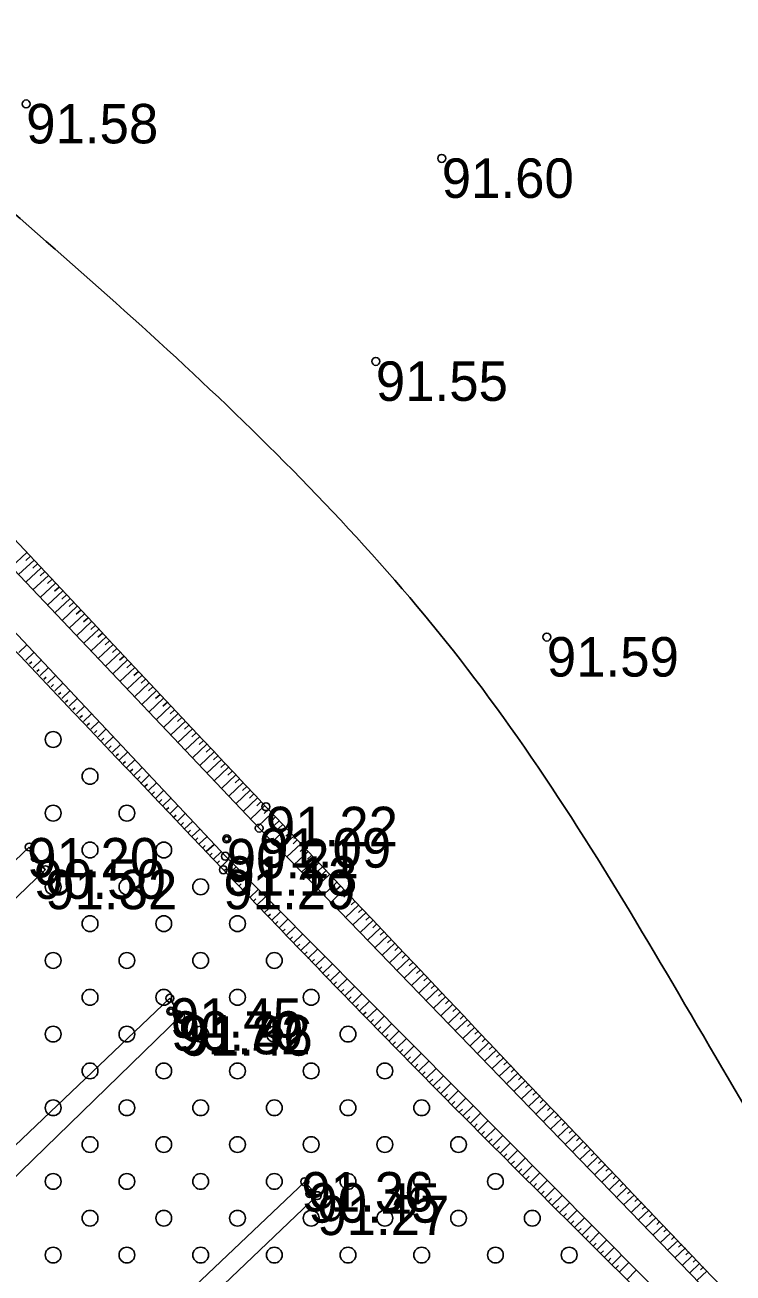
# Model space of a CAD drawing. Extents: x 316000 to 728450, y 314368 to 726000.
# Drawn here: x 726040.8 to 726108.1, y 315253.8 to 315372.4 of the extents above; entities that cross this region are included whole.
import ezdxf

# ---------------------------------------------------------------- set-up
doc = ezdxf.new("R2010")
doc.units = 0
for name, color, linetype in [('HIDG_ELEM_####_####_#', 7, 'Continuous'), ('HIDG_GRAV_####_####_#', 7, 'Continuous'), ('RELJ_AATZ_####_TKST_#', 7, 'Continuous'), ('RELJ_ELEM_####_####_#', 7, 'Continuous'), ('RELJ_HORZ_PAMT_####_#', 7, 'Continuous'), ('RELJ_NOGA_####_####_#', 7, 'Continuous'), ('TERT_ELEM_####_####_#', 7, 'Continuous')]:
    doc.layers.add(name, color=color, linetype=linetype)

msp = doc.modelspace()

# ---------------------------------------------------------------- linework, layer by layer
at = {"layer": 'HIDG_ELEM_####_####_#'}
for centre in [(726059.98, 315295.05), (726041.65, 315293.15), (726054.68, 315278.67), (726067.87, 315261.34)]:
    msp.add_circle(centre, 0.225, dxfattribs=at)
at = {"layer": 'HIDG_GRAV_####_####_#'}
for points in [[(726259.18, 315086.52), (726260.77, 315088.86), (726179.01, 315175.77), (726127.86, 315229.06), (726063.06, 315296.07), (725998.34, 315364.32), (725936.65, 315430.32), (725875.35, 315494.08), (725809.44, 315562.19), (725743.94, 315631.87)], [(725741.16, 315628.11), (725806.06, 315558.99), (725870.9, 315491.87), (725934.12, 315427.08), (725995.78, 315361.63), (726059.85, 315293.4), (726126.03, 315226.73), (726194.49, 315154.86), (726259.18, 315086.52)], [(726041.22, 315294.28), (726042.74, 315292.12), (725933.2, 315186.57), (725862.99, 315121.84), (725861.5, 315123.44), (725931.43, 315189.54), (726041.22, 315294.28)], [(726054.58, 315279.91), (726055.6, 315278.2), (725943.43, 315169.03), (725940.91, 315171.62), (726054.58, 315279.91)], [(726067.39, 315262.47), (726068.58, 315261.15), (725954.8, 315152.62), (725890.85, 315090.51), (725889.28, 315091.99), (725953.78, 315154.65), (726067.39, 315262.47)]]:
    msp.add_lwpolyline(points, dxfattribs=at)
at = {"layer": 'RELJ_ELEM_####_####_#'}
for centre in [(726040.93, 315364.9), (726080.4, 315359.72), (726074.14, 315340.43), (726090.38, 315314.23), (726063.7, 315298.11), (726063.06, 315296.07), (726059.98, 315295.05), (726041.22, 315294.28), (726059.85, 315293.4), (726042.74, 315292.12), (726059.66, 315292.12), (726054.58, 315279.91), (726054.68, 315278.67), (726055.39, 315278.33), (726055.6, 315278.2), (726067.39, 315262.47), (726067.87, 315261.34), (726068.58, 315261.15)]:
    msp.add_circle(centre, 0.375, dxfattribs=at)
at = {"layer": 'RELJ_HORZ_PAMT_####_#'}
for points in [[(726116.34, 315699.09), (726105.94, 315702.69), (726040.13, 315715), (725990.82, 315710.42), (725942.03, 315708.25), (725920.28, 315706.77), (725880.37, 315714.51), (725859.05, 315708.68), (725859.05, 315672.66), (725851.26, 315613.97), (725853.47, 315568.9), (725841, 315555.79), (725885.56, 315509.63), (725935.94, 315461.49), (725983.42, 315406.25), (726032.86, 315360.51), (726082.85, 315311.19), (726122.23, 315248.76), (726137.05, 315229.29), (726180.19, 315183.1), (726194.52, 315168.27), (726211.91, 315146.93), (726212.51, 315143.16)], [(726081.57, 315247.05), (726057.5, 315241.5), (726036.5, 315213.5), (725977, 315161), (725966.5, 315108.5), (725903.5, 315045.5), (725862.12, 315076.6), (725805.5, 315130), (725759.7, 315178.88), (725709.89, 315228.8), (725646.99, 315287.19), (725634.68, 315314.96), (725629.04, 315327.48), (725557.35, 315340.26), (725478.3, 315344.16)]]:
    msp.add_spline(points, degree=3, dxfattribs=at)
at = {"layer": 'RELJ_NOGA_####_####_#'}
for p, q in [((726041, 315322.28), (726039.52, 315320.89)), ((726041.68, 315321.55), (726040.21, 315320.17)), ((726041.34, 315321.91), (726040.89, 315321.5)), ((726042.02, 315321.18), (726041.58, 315320.77)), ((726042.36, 315320.82), (726040.89, 315319.44)), ((726043.05, 315320.09), (726041.58, 315318.72)), ((726042.7, 315320.45), (726042.26, 315320.04)), ((726043.73, 315319.36), (726042.27, 315317.99)), ((726043.39, 315319.72), (726042.95, 315319.31)), ((726044.07, 315318.99), (726043.63, 315318.58)), ((726044.41, 315318.63), (726042.96, 315317.26)), ((726045.1, 315317.9), (726043.65, 315316.54)), ((726044.76, 315318.26), (726044.32, 315317.85)), ((726045.44, 315317.53), (726045, 315317.13)), ((726045.78, 315317.17), (726044.34, 315315.81)), ((726046.46, 315316.44), (726045.02, 315315.09)), ((726046.12, 315316.8), (726045.69, 315316.4)), ((726047.15, 315315.71), (726045.71, 315314.36)), ((726046.81, 315316.07), (726046.38, 315315.67)), ((726047.49, 315315.34), (726047.06, 315314.94)), ((726047.83, 315314.98), (726046.4, 315313.64)), ((726048.52, 315314.25), (726047.09, 315312.91)), ((726048.17, 315314.61), (726047.75, 315314.21)), ((726040.22, 315312.77), (726040.98, 315313.49)), ((726040.9, 315312.04), (726041.66, 315312.76)), ((726049.2, 315313.52), (726047.78, 315312.18)), ((726048.86, 315313.88), (726048.43, 315313.48)), ((726049.89, 315312.79), (726048.47, 315311.46)), ((726049.54, 315313.16), (726049.12, 315312.75)), ((726041.24, 315311.68), (726041.47, 315311.89)), ((726041.59, 315311.31), (726042.35, 315312.03)), ((726050.57, 315312.06), (726049.15, 315310.73)), ((726050.23, 315312.43), (726049.8, 315312.03)), ((726050.91, 315311.7), (726050.49, 315311.3)), ((726041.93, 315310.95), (726042.16, 315311.16)), ((726042.27, 315310.58), (726043.03, 315311.3)), ((726042.61, 315310.22), (726042.84, 315310.43)), ((726042.96, 315309.86), (726043.72, 315310.57)), ((726051.25, 315311.33), (726049.84, 315310.01)), ((726051.94, 315310.6), (726050.53, 315309.28)), ((726051.6, 315310.97), (726051.17, 315310.57)), ((726043.3, 315309.49), (726043.53, 315309.71)), ((726043.64, 315309.13), (726044.4, 315309.84)), ((726052.62, 315309.87), (726051.22, 315308.55)), ((726052.28, 315310.24), (726051.86, 315309.84)), ((726052.97, 315309.51), (726052.54, 315309.11)), ((726043.99, 315308.76), (726044.21, 315308.98)), ((726044.33, 315308.4), (726045.09, 315309.11)), ((726044.67, 315308.03), (726044.9, 315308.25)), ((726045.01, 315307.67), (726045.77, 315308.38)), ((726053.31, 315309.15), (726051.91, 315307.83)), ((726053.99, 315308.42), (726052.59, 315307.1)), ((726053.65, 315308.78), (726053.23, 315308.39)), ((726054.34, 315308.05), (726053.92, 315307.66)), ((726045.36, 315307.31), (726045.58, 315307.52)), ((726045.7, 315306.94), (726046.46, 315307.66)), ((726046.04, 315306.58), (726046.27, 315306.79)), ((726046.38, 315306.21), (726047.14, 315306.93)), ((726054.68, 315307.69), (726053.28, 315306.38)), ((726055.36, 315306.96), (726053.97, 315305.65)), ((726055.02, 315307.32), (726054.6, 315306.93)), ((726046.73, 315305.85), (726046.95, 315306.06)), ((726047.07, 315305.49), (726047.83, 315306.2)), ((726056.05, 315306.23), (726054.66, 315304.93)), ((726055.71, 315306.6), (726055.29, 315306.2)), ((726056.39, 315305.87), (726055.97, 315305.48)), ((726047.41, 315305.12), (726047.64, 315305.34)), ((726047.76, 315304.76), (726048.51, 315305.47)), ((726048.1, 315304.39), (726048.32, 315304.61)), ((726048.44, 315304.03), (726049.19, 315304.74)), ((726056.73, 315305.5), (726055.35, 315304.2)), ((726057.42, 315304.77), (726056.04, 315303.47)), ((726057.08, 315305.14), (726056.66, 315304.75)), ((726048.78, 315303.67), (726049.01, 315303.88)), ((726049.13, 315303.3), (726049.88, 315304.01)), ((726049.81, 315302.57), (726050.56, 315303.28)), ((726058.1, 315304.05), (726056.72, 315302.75)), ((726057.76, 315304.41), (726057.35, 315304.02)), ((726058.79, 315303.32), (726057.41, 315302.02)), ((726058.45, 315303.68), (726058.03, 315303.29)), ((726049.47, 315302.94), (726049.69, 315303.15)), ((726050.15, 315302.21), (726050.38, 315302.42)), ((726050.5, 315301.85), (726051.25, 315302.55)), ((726059.48, 315302.59), (726058.1, 315301.3)), ((726059.13, 315302.95), (726058.72, 315302.57)), ((726059.82, 315302.23), (726059.41, 315301.84)), ((726050.84, 315301.48), (726051.07, 315301.69)), ((726051.18, 315301.12), (726051.93, 315301.82)), ((726051.53, 315300.75), (726051.75, 315300.97)), ((726051.87, 315300.39), (726052.62, 315301.1)), ((726060.16, 315301.86), (726058.79, 315300.57)), ((726060.85, 315301.14), (726059.48, 315299.84)), ((726060.5, 315301.5), (726060.09, 315301.11)), ((726052.21, 315300.03), (726052.44, 315300.24)), ((726052.55, 315299.66), (726053.3, 315300.37)), ((726061.53, 315300.41), (726060.17, 315299.12)), ((726061.19, 315300.77), (726060.78, 315300.38)), ((726062.22, 315299.68), (726060.85, 315298.39)), ((726061.88, 315300.04), (726061.47, 315299.66)), ((726052.9, 315299.3), (726053.12, 315299.51)), ((726053.24, 315298.93), (726053.99, 315299.64)), ((726053.58, 315298.57), (726053.81, 315298.78)), ((726053.93, 315298.21), (726054.67, 315298.91)), ((726062.91, 315298.95), (726061.54, 315297.67)), ((726062.56, 315299.32), (726062.15, 315298.93)), ((726063.25, 315298.59), (726062.84, 315298.2)), ((726054.27, 315297.84), (726054.49, 315298.05)), ((726054.61, 315297.48), (726055.35, 315298.18)), ((726054.95, 315297.11), (726055.18, 315297.32)), ((726055.3, 315296.75), (726056.04, 315297.45)), ((726063.59, 315298.23), (726062.23, 315296.94)), ((726064.28, 315297.5), (726062.92, 315296.22)), ((726063.94, 315297.86), (726063.53, 315297.48)), ((726055.64, 315296.39), (726055.86, 315296.6)), ((726055.98, 315296.02), (726056.72, 315296.72)), ((726064.97, 315296.77), (726063.61, 315295.5)), ((726064.62, 315297.14), (726064.22, 315296.75)), ((726065.31, 315296.41), (726064.9, 315296.03)), ((726056.33, 315295.66), (726056.55, 315295.87)), ((726056.67, 315295.29), (726057.41, 315295.99)), ((726057.01, 315294.93), (726057.23, 315295.14)), ((726057.35, 315294.57), (726058.09, 315295.26)), ((726065.65, 315296.04), (726064.31, 315294.78)), ((726066.34, 315295.32), (726065, 315294.06)), ((726066, 315295.68), (726065.59, 315295.3)), ((726066.68, 315294.95), (726066.28, 315294.58)), ((726057.7, 315294.2), (726057.92, 315294.41)), ((726058.04, 315293.84), (726058.78, 315294.53)), ((726058.73, 315293.11), (726059.46, 315293.81)), ((726067.03, 315294.59), (726065.7, 315293.34)), ((726067.71, 315293.86), (726066.39, 315292.62)), ((726067.37, 315294.23), (726066.97, 315293.85)), ((726058.38, 315293.48), (726058.6, 315293.68)), ((726059.07, 315292.75), (726059.29, 315292.96)), ((726059.41, 315292.38), (726060.16, 315293.08)), ((726068.4, 315293.14), (726067.09, 315291.9)), ((726068.06, 315293.5), (726067.66, 315293.13)), ((726068.74, 315292.77), (726068.35, 315292.4)), ((726059.75, 315292.02), (726059.98, 315292.23)), ((726060.1, 315291.66), (726060.86, 315292.37)), ((726060.44, 315291.29), (726060.67, 315291.51)), ((726060.78, 315290.93), (726061.56, 315291.67)), ((726069.09, 315292.41), (726067.79, 315291.18)), ((726069.77, 315291.69), (726068.48, 315290.46)), ((726069.43, 315292.05), (726069.04, 315291.68)), ((726061.13, 315290.57), (726061.36, 315290.79)), ((726061.47, 315290.2), (726062.27, 315290.96)), ((726062.16, 315289.48), (726062.97, 315290.25)), ((726070.46, 315290.96), (726069.18, 315289.74)), ((726070.12, 315291.32), (726069.73, 315290.96)), ((726071.15, 315290.23), (726069.87, 315289.02)), ((726070.81, 315290.6), (726070.42, 315290.23)), ((726061.81, 315289.84), (726062.06, 315290.07)), ((726062.5, 315289.11), (726062.75, 315289.35)), ((726062.85, 315288.75), (726063.67, 315289.54)), ((726071.84, 315289.51), (726070.57, 315288.3)), ((726071.49, 315289.87), (726071.11, 315289.51)), ((726072.18, 315289.14), (726071.8, 315288.78)), ((726063.19, 315288.39), (726063.44, 315288.63)), ((726063.54, 315288.03), (726064.38, 315288.83)), ((726063.88, 315287.67), (726064.14, 315287.91)), ((726064.23, 315287.3), (726065.08, 315288.12)), ((726072.52, 315288.78), (726071.26, 315287.59)), ((726073.21, 315288.05), (726071.96, 315286.87)), ((726072.87, 315288.42), (726072.49, 315288.06)), ((726064.57, 315286.94), (726064.83, 315287.19)), ((726064.92, 315286.58), (726065.79, 315287.41)), ((726065.61, 315285.86), (726066.49, 315286.7)), ((726073.9, 315287.33), (726072.65, 315286.15)), ((726073.56, 315287.69), (726073.18, 315287.34)), ((726074.24, 315286.97), (726073.87, 315286.61)), ((726065.26, 315286.22), (726065.53, 315286.47)), ((726065.96, 315285.5), (726066.22, 315285.75)), ((726066.3, 315285.14), (726067.19, 315285.99)), ((726074.59, 315286.6), (726073.35, 315285.43)), ((726075.27, 315285.88), (726074.04, 315284.71)), ((726074.93, 315286.24), (726074.56, 315285.89)), ((726075.62, 315285.51), (726075.25, 315285.16)), ((726066.65, 315284.78), (726066.92, 315285.04)), ((726067, 315284.42), (726067.9, 315285.29)), ((726067.34, 315284.06), (726067.62, 315284.32)), ((726067.69, 315283.7), (726068.6, 315284.58)), ((726075.96, 315285.15), (726074.74, 315283.99)), ((726076.65, 315284.42), (726075.43, 315283.27)), ((726076.31, 315284.79), (726075.94, 315284.44)), ((726068.04, 315283.34), (726068.31, 315283.6)), ((726068.39, 315282.98), (726069.31, 315283.87)), ((726069.08, 315282.26), (726070.01, 315283.16)), ((726077.34, 315283.7), (726076.13, 315282.55)), ((726076.99, 315284.06), (726076.63, 315283.72)), ((726077.68, 315283.34), (726077.32, 315282.99)), ((726068.73, 315282.62), (726069.01, 315282.89)), ((726069.43, 315281.9), (726069.71, 315282.17)), ((726069.78, 315281.54), (726070.71, 315282.45)), ((726078.03, 315282.97), (726076.82, 315281.83)), ((726078.72, 315282.25), (726077.52, 315281.11)), ((726078.37, 315282.61), (726078.01, 315282.27)), ((726079.06, 315281.89), (726078.7, 315281.55)), ((726070.13, 315281.18), (726070.41, 315281.46)), ((726070.48, 315280.83), (726071.42, 315281.74)), ((726070.82, 315280.47), (726071.11, 315280.74)), ((726071.17, 315280.11), (726072.12, 315281.03)), ((726079.4, 315281.52), (726078.22, 315280.39)), ((726080.09, 315280.8), (726078.91, 315279.68)), ((726079.75, 315281.16), (726079.39, 315280.82)), ((726071.52, 315279.75), (726071.81, 315280.03)), ((726071.87, 315279.39), (726072.82, 315280.32)), ((726072.57, 315278.68), (726073.53, 315279.62)), ((726080.78, 315280.07), (726079.61, 315278.96)), ((726080.44, 315280.43), (726080.08, 315280.1)), ((726081.12, 315279.71), (726080.77, 315279.38)), ((726072.22, 315279.04), (726072.51, 315279.32)), ((726072.92, 315278.32), (726073.21, 315278.6)), ((726073.27, 315277.97), (726074.23, 315278.91)), ((726081.47, 315279.35), (726080.3, 315278.24)), ((726082.16, 315278.62), (726081, 315277.52)), ((726081.81, 315278.98), (726081.46, 315278.65)), ((726073.62, 315277.61), (726073.91, 315277.89)), ((726073.97, 315277.25), (726074.93, 315278.2)), ((726074.32, 315276.9), (726074.61, 315277.18)), ((726074.68, 315276.54), (726075.64, 315277.49)), ((726082.85, 315277.9), (726081.69, 315276.8)), ((726082.5, 315278.26), (726082.15, 315277.93)), ((726083.54, 315277.17), (726082.39, 315276.08)), ((726083.19, 315277.53), (726082.85, 315277.21)), ((726075.03, 315276.19), (726075.32, 315276.47)), ((726075.38, 315275.83), (726076.34, 315276.78)), ((726076.08, 315275.12), (726077.04, 315276.07)), ((726084.22, 315276.45), (726083.08, 315275.36)), ((726083.88, 315276.81), (726083.54, 315276.48)), ((726084.57, 315276.08), (726084.23, 315275.76)), ((726075.73, 315275.47), (726076.02, 315275.76)), ((726076.43, 315274.76), (726076.72, 315275.05)), ((726076.79, 315274.41), (726077.75, 315275.36)), ((726084.91, 315275.72), (726083.78, 315274.64)), ((726085.6, 315275), (726084.47, 315273.92)), ((726085.26, 315275.36), (726084.92, 315275.04)), ((726077.14, 315274.05), (726077.43, 315274.34)), ((726077.49, 315273.7), (726078.45, 315274.65)), ((726077.84, 315273.34), (726078.13, 315273.63)), ((726078.19, 315272.99), (726079.16, 315273.94)), ((726086.29, 315274.27), (726085.17, 315273.2)), ((726085.95, 315274.64), (726085.61, 315274.31)), ((726086.64, 315273.91), (726086.3, 315273.59)), ((726078.55, 315272.63), (726078.83, 315272.92)), ((726078.9, 315272.28), (726079.86, 315273.23)), ((726079.6, 315271.57), (726080.57, 315272.53)), ((726086.98, 315273.55), (726085.86, 315272.49)), ((726087.67, 315272.82), (726086.56, 315271.77)), ((726087.32, 315273.19), (726086.99, 315272.87)), ((726088.01, 315272.46), (726087.68, 315272.15)), ((726079.25, 315271.92), (726079.54, 315272.21)), ((726079.95, 315271.21), (726080.24, 315271.5)), ((726080.31, 315270.86), (726081.27, 315271.82)), ((726088.36, 315272.1), (726087.25, 315271.05)), ((726089.05, 315271.37), (726087.95, 315270.33)), ((726088.7, 315271.74), (726088.37, 315271.42)), ((726080.66, 315270.5), (726080.95, 315270.79)), ((726081.01, 315270.15), (726081.97, 315271.11)), ((726081.36, 315269.8), (726081.65, 315270.08)), ((726081.72, 315269.44), (726082.68, 315270.4)), ((726089.74, 315270.65), (726088.64, 315269.61)), ((726089.39, 315271.01), (726089.06, 315270.7)), ((726090.08, 315270.29), (726089.76, 315269.98)), ((726082.07, 315269.09), (726082.36, 315269.37)), ((726082.42, 315268.73), (726083.38, 315269.69)), ((726083.13, 315268.02), (726084.09, 315268.98)), ((726090.43, 315269.93), (726089.34, 315268.89)), ((726091.12, 315269.2), (726090.03, 315268.17)), ((726090.77, 315269.56), (726090.45, 315269.25)), ((726091.46, 315268.84), (726091.14, 315268.53)), ((726082.78, 315268.38), (726083.06, 315268.66)), ((726083.48, 315267.67), (726083.77, 315267.96)), ((726083.83, 315267.31), (726084.79, 315268.27)), ((726091.81, 315268.48), (726090.73, 315267.45)), ((726092.5, 315267.75), (726091.43, 315266.73)), ((726092.15, 315268.12), (726091.83, 315267.81)), ((726084.19, 315266.96), (726084.47, 315267.25)), ((726084.54, 315266.61), (726085.5, 315267.56)), ((726084.89, 315266.25), (726085.18, 315266.54)), ((726085.25, 315265.9), (726086.2, 315266.85)), ((726093.19, 315267.03), (726092.12, 315266.01)), ((726092.84, 315267.39), (726092.52, 315267.09)), ((726093.53, 315266.67), (726093.21, 315266.36)), ((726085.6, 315265.54), (726085.88, 315265.83)), ((726085.95, 315265.19), (726086.9, 315266.14)), ((726086.66, 315264.48), (726087.61, 315265.43)), ((726093.88, 315266.31), (726092.82, 315265.3)), ((726094.57, 315265.58), (726093.51, 315264.58)), ((726094.22, 315265.94), (726093.9, 315265.64)), ((726086.3, 315264.84), (726086.59, 315265.12)), ((726087.01, 315264.13), (726087.3, 315264.41)), ((726087.36, 315263.77), (726088.31, 315264.72)), ((726095.26, 315264.86), (726094.21, 315263.86)), ((726094.91, 315265.22), (726094.6, 315264.92)), ((726095.95, 315264.13), (726094.9, 315263.14)), ((726095.6, 315264.5), (726095.29, 315264.2)), ((726087.72, 315263.42), (726088, 315263.7)), ((726088.07, 315263.07), (726089.02, 315264.01)), ((726088.42, 315262.71), (726088.71, 315263)), ((726088.78, 315262.36), (726089.72, 315263.3)), ((726096.64, 315263.41), (726095.6, 315262.42)), ((726096.29, 315263.77), (726095.98, 315263.47)), ((726096.98, 315263.05), (726096.67, 315262.75)), ((726089.13, 315262), (726089.41, 315262.29)), ((726089.48, 315261.65), (726090.43, 315262.59)), ((726090.19, 315260.94), (726091.13, 315261.88)), ((726097.33, 315262.69), (726096.29, 315261.7)), ((726098.02, 315261.96), (726096.99, 315260.98)), ((726097.67, 315262.33), (726097.36, 315262.03)), ((726089.84, 315261.3), (726090.12, 315261.58)), ((726090.54, 315260.59), (726090.82, 315260.87)), ((726090.9, 315260.23), (726091.84, 315261.17)), ((726098.71, 315261.24), (726097.68, 315260.26)), ((726098.36, 315261.6), (726098.05, 315261.31)), ((726099.05, 315260.88), (726098.75, 315260.59)), ((726091.25, 315259.88), (726091.53, 315260.16)), ((726091.6, 315259.53), (726092.54, 315260.46)), ((726091.96, 315259.17), (726092.24, 315259.45)), ((726092.31, 315258.82), (726093.24, 315259.75)), ((726099.4, 315260.52), (726098.38, 315259.54)), ((726100.09, 315259.79), (726099.07, 315258.83)), ((726099.74, 315260.16), (726099.44, 315259.86)), ((726100.43, 315259.43), (726100.13, 315259.14)), ((726092.66, 315258.47), (726092.94, 315258.75)), ((726093.02, 315258.11), (726093.95, 315259.04)), ((726093.72, 315257.4), (726094.65, 315258.33)), ((726100.78, 315259.07), (726099.77, 315258.11)), ((726101.47, 315258.35), (726100.46, 315257.39)), ((726101.12, 315258.71), (726100.82, 315258.42)), ((726093.37, 315257.76), (726093.65, 315258.04)), ((726094.08, 315257.05), (726094.35, 315257.33)), ((726094.43, 315256.7), (726095.36, 315257.63)), ((726102.16, 315257.62), (726101.16, 315256.67)), ((726101.81, 315257.99), (726101.51, 315257.7)), ((726102.51, 315257.26), (726102.21, 315256.98)), ((726094.78, 315256.34), (726095.06, 315256.62)), ((726095.14, 315255.99), (726096.06, 315256.92)), ((726095.49, 315255.64), (726095.77, 315255.91)), ((726095.84, 315255.28), (726096.77, 315256.21)), ((726102.85, 315256.9), (726101.85, 315255.95)), ((726103.54, 315256.18), (726102.55, 315255.23)), ((726103.2, 315256.54), (726102.9, 315256.25)), ((726103.89, 315255.82), (726103.59, 315255.53)), ((726096.2, 315254.93), (726096.47, 315255.21)), ((726096.55, 315254.58), (726097.47, 315255.5)), ((726097.26, 315253.87), (726098.17, 315254.79)), ((726104.23, 315255.46), (726103.24, 315254.51)), ((726104.92, 315254.73), (726103.94, 315253.79)), ((726104.58, 315255.09), (726104.28, 315254.81)), ((726096.91, 315254.22), (726097.18, 315254.5)), ((726097.97, 315253.16), (726098.88, 315254.08)), ((726105.61, 315254.01), (726104.64, 315253.07)), ((726105.27, 315254.37), (726104.97, 315254.09))]:
    msp.add_line(p, q, dxfattribs=at)
for points in [[(726259.12, 315084.51), (726262.72, 315089.26), (726261.56, 315090.84), (726260.2, 315092.42), (726257.29, 315095.53), (726218.91, 315136.38), (726180.31, 315176.84), (726128.67, 315229.97), (726063.7, 315298.11), (725999.9, 315366.09), (725937.21, 315432.09), (725876.35, 315495.23), (725810.58, 315563.08), (725744.7, 315632.91)], [(725740.86, 315626.98), (725805.54, 315558.12), (725870.39, 315491.15), (725932.8, 315426.8), (725994.98, 315360.84), (726059.66, 315292.12), (726075.75, 315275.46), (726092.08, 315259.04), (726108.47, 315242.67), (726124.69, 315226.14), (726193.27, 315154.03), (726250.06, 315092.6), (726256.32, 315085.83), (726258.82, 315084.29), (726259.12, 315084.51)]]:
    msp.add_spline(points, degree=3, dxfattribs=at)
at = {"layer": 'TERT_ELEM_####_####_#'}
for centre in [(726043.5, 315304.5), (726047, 315301), (726043.5, 315297.5), (726050.5, 315297.5), (726047, 315294), (726054, 315294), (726043.5, 315290.5), (726050.5, 315290.5), (726057.5, 315290.5), (726047, 315287), (726054, 315287), (726061, 315287), (726043.5, 315283.5), (726050.5, 315283.5), (726057.5, 315283.5), (726064.5, 315283.5), (726047, 315280), (726054, 315280), (726061, 315280), (726068, 315280), (726043.5, 315276.5), (726050.5, 315276.5), (726057.5, 315276.5), (726064.5, 315276.5), (726071.5, 315276.5), (726047, 315273), (726054, 315273), (726061, 315273), (726068, 315273), (726075, 315273), (726043.5, 315269.5), (726050.5, 315269.5), (726057.5, 315269.5), (726064.5, 315269.5), (726071.5, 315269.5), (726078.5, 315269.5), (726047, 315266), (726054, 315266), (726061, 315266), (726068, 315266), (726075, 315266), (726082, 315266), (726043.5, 315262.5), (726050.5, 315262.5), (726057.5, 315262.5), (726064.5, 315262.5), (726071.5, 315262.5), (726078.5, 315262.5), (726085.5, 315262.5), (726047, 315259), (726054, 315259), (726061, 315259), (726068, 315259), (726075, 315259), (726082, 315259), (726089, 315259), (726043.5, 315255.5), (726050.5, 315255.5), (726057.5, 315255.5), (726064.5, 315255.5), (726071.5, 315255.5), (726078.5, 315255.5), (726085.5, 315255.5), (726092.5, 315255.5)]:
    msp.add_circle(centre, 0.75, dxfattribs=at)

# ---------------------------------------------------------------- texts
at = {"layer": 'RELJ_AATZ_####_TKST_#'}
for s, p in [('91.58', (726040.93, 315361.15)), ('91.60', (726080.4, 315355.97)), ('91.55', (726074.14, 315336.68)), ('91.59', (726090.38, 315310.48)), ('91.22', (726063.7, 315294.36)), ('91.09', (726063.06, 315292.32)), ('91.20', (726041.02, 315291.39)), ('90.21', (726059.98, 315291.3)), ('90.50', (726041.65, 315289.35)), ('91.13', (726059.85, 315289.65)), ('91.32', (726042.74, 315288.37)), ('91.29', (726059.66, 315288.37)), ('91.45', (726054.58, 315276.16)), ('90.70', (726054.68, 315274.92)), ('91.32', (726055.39, 315274.58)), ('91.46', (726055.6, 315274.45)), ('91.36', (726067.07, 315259.64)), ('90.45', (726067.73, 315258.58)), ('91.27', (726068.58, 315257.4))]:
    msp.add_text(s, height=3.75, dxfattribs=at).set_placement(p)

doc.saveas('drawing.dxf')
